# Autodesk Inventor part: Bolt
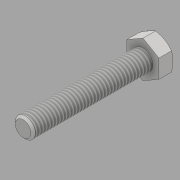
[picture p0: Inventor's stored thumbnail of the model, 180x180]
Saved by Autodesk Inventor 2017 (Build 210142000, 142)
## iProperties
Created: 2016-05
Part Number: Bolt
Material: Generic
Document SubType Name: Modeling
Designer: CADCIM
Density: 1 g/cm^3
Appearance: Default
Author: CADCIM
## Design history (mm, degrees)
sketch "Sketch1"
  geometry: L1 (3.604, -2.072)-(0.007, -4.157); L2 (0.007, -4.157)-(-3.596, -2.085); L3 (-3.596, -2.085)-(-3.604, 2.072); L4 (-3.604, 2.072)-(-0.007, 4.157); L5 (-0.007, 4.157)-(3.596, 2.085); L6 (3.596, 2.085)-(3.604, -2.072); 2 further points
  constraints: 12 end point, 1 coincident, 13 other
  dimensions: "d0" = 7.2 distance between parallel lines of L3 L6
extrude "Extrusion1" new body sketch "Sketch1" distance "d1" = 3.15; taper "d2" = 0 deg
sketch "Sketch2"
  geometry: C1 r 2.25 at (0, 0); 1 further point
  constraints: 1 centre point, 1 coincident
  dimensions: "d3" = 4.5 diameter of C1
extrude "Extrusion2" join sketch "Sketch2" distance "d4" = 27; taper "d5" = 0 deg
thread "Thread1" dims "d6" = 10, "d7" = 0
chamfer "Chamfer1" distance "d8" = 0.5; stored, may be unused: second distance "d9" = 2, angle "d10" = 45 deg
sketch "Sketch3"
  geometry: L1 (0.007, -4.157)-(3.604, -2.072) reference; C1 r 3.6 at (0, 0); 1 further point
  constraints: 1 centre point, 1 coincident, 1 tangent
extrude "Extrusion3" sketch "Sketch3" distance "d11" = 41; taper "d12" = 60 deg
body "Solid1"
